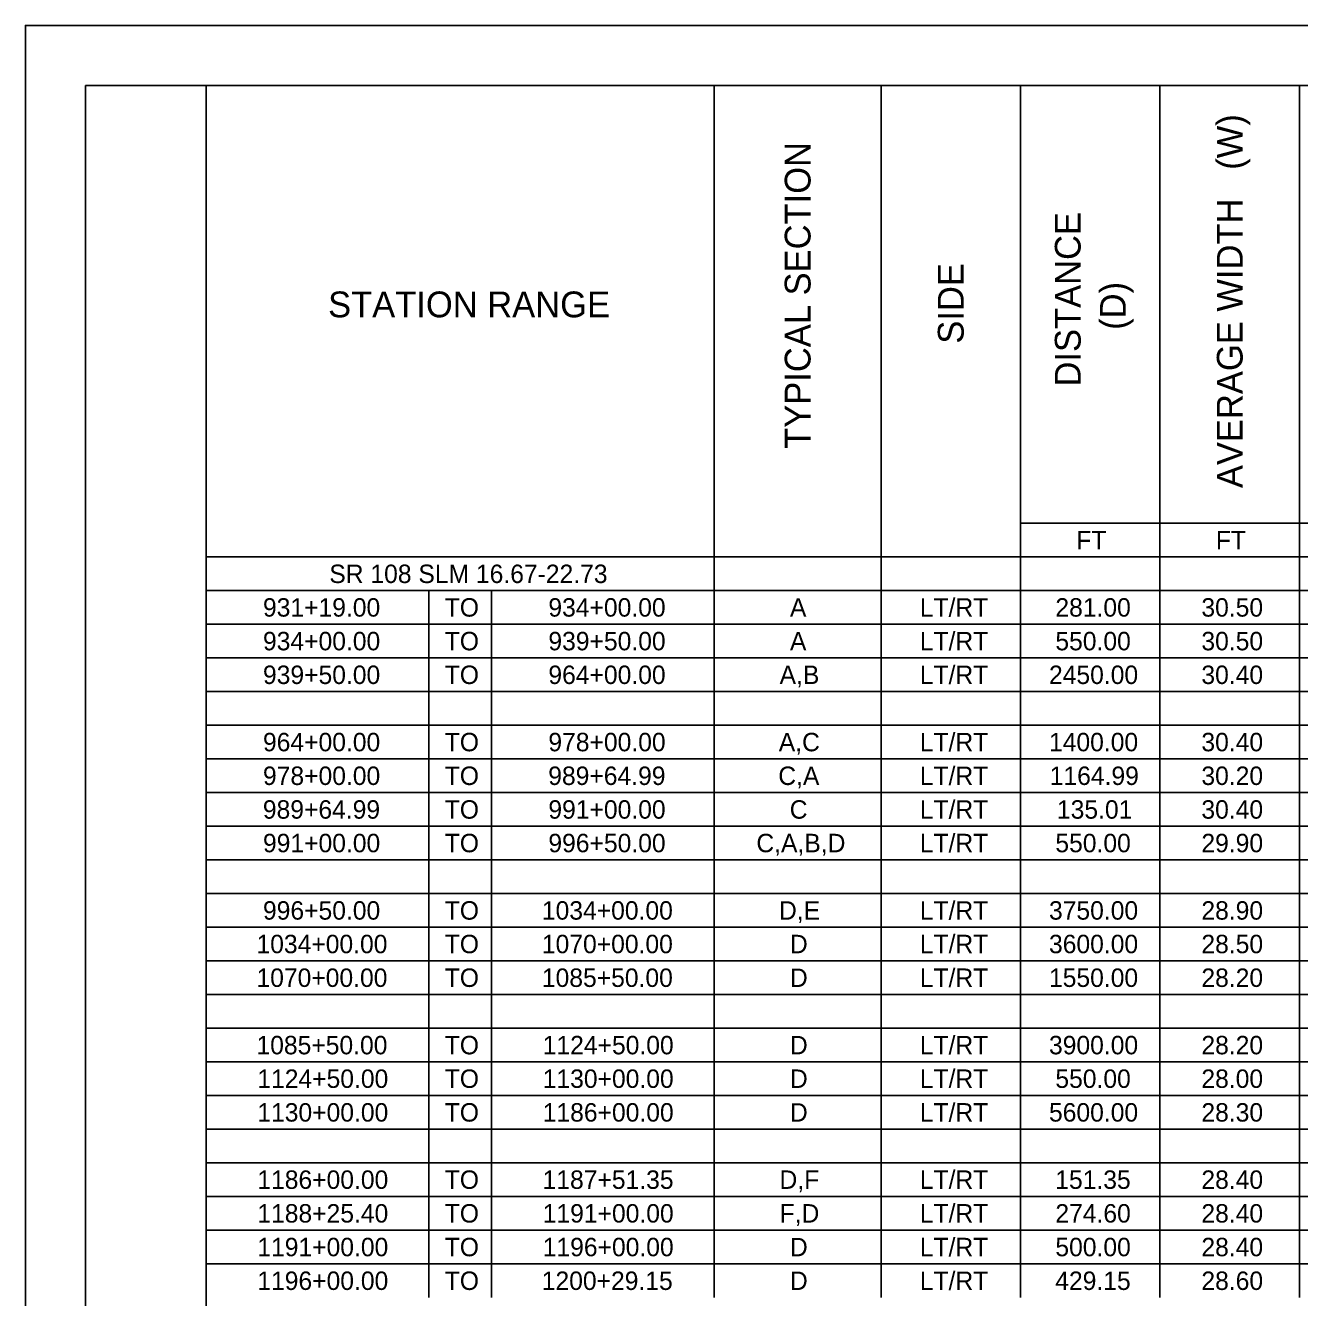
# Model space of a CAD drawing. Extents: x 0 to 34.4, y 0 to 47.
# Drawn here: x 0 to 10.58, y 11.43 to 22 of the extents above; entities that cross this region are included whole.
import ezdxf

# ---------------------------------------------------------------- set-up
doc = ezdxf.new("R2010")
doc.units = 0
for name, color, linetype in [('SH_Border', 7, 'Continuous'), ('SH_Cut_Line', 7, 'Continuous'), ('SH_Text', 7, 'Continuous')]:
    doc.layers.add(name, color=color, linetype=linetype)

msp = doc.modelspace()

# ---------------------------------------------------------------- linework, layer by layer
at = {"layer": 'SH_Border'}
for points in [[(0.5, 21.5), (1.5, 21.5), (1.5, 0.5), (0.5, 0.5)], [(1.5, 21.5), (33.5, 21.5), (33.5, 0.5), (1.5, 0.5)]]:
    msp.add_lwpolyline(points, close=True, dxfattribs=at)
at = {"layer": 'SH_Cut_Line'}
msp.add_lwpolyline([(0, 0), (34, 0), (34, 22), (0, 22)], close=True, dxfattribs=at)
at = {"layer": 'SH_Text'}
for p, q in [((1.5, 21.5), (3.871, 21.5)), ((1.5, 21.5), (1.5, 21.22)), ((3.871, 21.5), (8.267, 21.5)), ((5.722, 21.5), (5.722, 21.22)), ((7.108, 21.5), (7.108, 21.22)), ((8.267, 21.5), (10.584, 21.5)), ((8.267, 21.5), (8.267, 21.22)), ((9.425, 21.5), (9.425, 21.22)), ((10.584, 21.5), (11.743, 21.5)), ((10.584, 21.5), (10.584, 21.22)), ((1.5, 21.22), (1.5, 20.941)), ((5.722, 21.22), (5.722, 20.941)), ((7.108, 21.22), (7.108, 20.941)), ((8.267, 21.22), (8.267, 20.941)), ((9.425, 21.22), (9.425, 20.941)), ((10.584, 21.22), (10.584, 20.941)), ((1.5, 20.941), (1.5, 20.661)), ((5.722, 20.941), (5.722, 20.661)), ((7.108, 20.941), (7.108, 20.661)), ((8.267, 20.941), (8.267, 20.661)), ((9.425, 20.941), (9.425, 20.661)), ((10.584, 20.941), (10.584, 20.661)), ((1.5, 20.661), (1.5, 20.101)), ((5.722, 20.661), (5.722, 20.101)), ((7.108, 20.661), (7.108, 20.101)), ((8.267, 20.661), (8.267, 20.101)), ((9.425, 20.661), (9.425, 20.101)), ((10.584, 20.661), (10.584, 20.101)), ((1.5, 20.101), (1.5, 19.822)), ((5.722, 20.101), (5.722, 19.822)), ((7.108, 20.101), (7.108, 19.822)), ((8.267, 20.101), (8.267, 19.822)), ((9.425, 20.101), (9.425, 19.822)), ((10.584, 20.101), (10.584, 19.822)), ((1.5, 19.822), (1.5, 19.542)), ((5.722, 19.822), (5.722, 19.542)), ((7.108, 19.822), (7.108, 19.542)), ((8.267, 19.822), (8.267, 19.542)), ((9.425, 19.822), (9.425, 19.542)), ((10.584, 19.822), (10.584, 19.542)), ((1.5, 19.542), (1.5, 19.262)), ((5.722, 19.542), (5.722, 19.262)), ((7.108, 19.542), (7.108, 19.262)), ((8.267, 19.542), (8.267, 19.262)), ((9.425, 19.542), (9.425, 19.262)), ((10.584, 19.542), (10.584, 19.262)), ((1.5, 19.262), (1.5, 18.983)), ((5.722, 19.262), (5.722, 18.983)), ((7.108, 19.262), (7.108, 18.983)), ((8.267, 19.262), (8.267, 18.983)), ((9.425, 19.262), (9.425, 18.983)), ((10.584, 19.262), (10.584, 18.983)), ((1.5, 18.983), (1.5, 18.703)), ((5.722, 18.983), (5.722, 18.703)), ((7.108, 18.983), (7.108, 18.703)), ((8.267, 18.983), (8.267, 18.703)), ((9.425, 18.983), (9.425, 18.703)), ((10.584, 18.983), (10.584, 18.703)), ((1.5, 18.703), (1.5, 18.423)), ((5.722, 18.703), (5.722, 18.423)), ((7.108, 18.703), (7.108, 18.423)), ((8.267, 18.703), (8.267, 18.423)), ((9.425, 18.703), (9.425, 18.423)), ((10.584, 18.703), (10.584, 18.423)), ((1.5, 18.423), (1.5, 18.143)), ((5.722, 18.423), (5.722, 18.143)), ((7.108, 18.423), (7.108, 18.143)), ((8.267, 18.423), (8.267, 18.143)), ((9.425, 18.423), (9.425, 18.143)), ((10.584, 18.423), (10.584, 18.143)), ((1.5, 18.143), (1.5, 17.864)), ((5.722, 18.143), (5.722, 17.864)), ((7.108, 18.143), (7.108, 17.864)), ((8.267, 18.143), (8.267, 17.864)), ((9.425, 18.143), (9.425, 17.864)), ((10.584, 18.143), (10.584, 17.864)), ((1.5, 17.864), (1.5, 17.584)), ((5.722, 17.864), (5.722, 17.584)), ((7.108, 17.864), (7.108, 17.584)), ((8.267, 17.864), (10.584, 17.864)), ((8.267, 17.864), (8.267, 17.584)), ((9.425, 17.864), (9.425, 17.584)), ((10.584, 17.864), (11.743, 17.864)), ((10.584, 17.864), (10.584, 17.584)), ((1.5, 17.584), (3.871, 17.584)), ((1.5, 17.584), (1.5, 17.304)), ((3.871, 17.584), (8.267, 17.584)), ((5.722, 17.584), (5.722, 17.304)), ((7.108, 17.584), (7.108, 17.304)), ((8.267, 17.584), (10.584, 17.584)), ((8.267, 17.584), (8.267, 17.304)), ((9.425, 17.584), (9.425, 17.304)), ((10.584, 17.584), (11.743, 17.584)), ((10.584, 17.584), (10.584, 17.304)), ((1.5, 17.304), (3.871, 17.304)), ((1.5, 17.304), (1.5, 17.024)), ((3.351, 17.304), (3.351, 17.024)), ((3.871, 17.304), (8.267, 17.304)), ((3.871, 17.304), (3.871, 17.024)), ((5.722, 17.304), (5.722, 17.024)), ((7.108, 17.304), (7.108, 17.024)), ((8.267, 17.304), (10.584, 17.304)), ((8.267, 17.304), (8.267, 17.024)), ((9.425, 17.304), (9.425, 17.024)), ((10.584, 17.304), (11.743, 17.304)), ((10.584, 17.304), (10.584, 17.024)), ((1.5, 17.024), (3.871, 17.024)), ((1.5, 17.024), (1.5, 16.745)), ((3.351, 17.024), (3.351, 16.745)), ((3.871, 17.024), (8.267, 17.024)), ((3.871, 17.024), (3.871, 16.745)), ((5.722, 17.024), (5.722, 16.745)), ((7.108, 17.024), (7.108, 16.745)), ((8.267, 17.024), (10.584, 17.024)), ((8.267, 17.024), (8.267, 16.745)), ((9.425, 17.024), (9.425, 16.745)), ((10.584, 17.024), (11.743, 17.024)), ((10.584, 17.024), (10.584, 16.745)), ((1.5, 16.745), (3.871, 16.745)), ((1.5, 16.745), (1.5, 16.185)), ((3.351, 16.745), (3.351, 16.185)), ((3.871, 16.745), (8.267, 16.745)), ((3.871, 16.745), (3.871, 16.185)), ((5.722, 16.745), (5.722, 16.185)), ((7.108, 16.745), (7.108, 16.185)), ((8.267, 16.745), (10.584, 16.745)), ((8.267, 16.745), (8.267, 16.185)), ((9.425, 16.745), (9.425, 16.185)), ((10.584, 16.745), (11.743, 16.745)), ((10.584, 16.745), (10.584, 16.185)), ((1.5, 16.465), (3.871, 16.465)), ((3.871, 16.465), (8.267, 16.465)), ((8.267, 16.465), (10.584, 16.465)), ((10.584, 16.465), (11.743, 16.465)), ((1.5, 16.185), (3.871, 16.185)), ((1.5, 16.185), (1.5, 15.906)), ((3.351, 16.185), (3.351, 15.906)), ((3.871, 16.185), (8.267, 16.185)), ((3.871, 16.185), (3.871, 15.906)), ((5.722, 16.185), (5.722, 15.906)), ((7.108, 16.185), (7.108, 15.906)), ((8.267, 16.185), (10.584, 16.185)), ((8.267, 16.185), (8.267, 15.906)), ((9.425, 16.185), (9.425, 15.906)), ((10.584, 16.185), (11.743, 16.185)), ((10.584, 16.185), (10.584, 15.906)), ((1.5, 15.906), (3.871, 15.906)), ((1.5, 15.906), (1.5, 15.626)), ((3.351, 15.906), (3.351, 15.626)), ((3.871, 15.906), (8.267, 15.906)), ((3.871, 15.906), (3.871, 15.626)), ((5.722, 15.906), (5.722, 15.626)), ((7.108, 15.906), (7.108, 15.626)), ((8.267, 15.906), (10.584, 15.906)), ((8.267, 15.906), (8.267, 15.626)), ((9.425, 15.906), (9.425, 15.626)), ((10.584, 15.906), (11.743, 15.906)), ((10.584, 15.906), (10.584, 15.626)), ((1.5, 15.626), (3.871, 15.626)), ((1.5, 15.626), (1.5, 15.346)), ((3.351, 15.626), (3.351, 15.346)), ((3.871, 15.626), (8.267, 15.626)), ((3.871, 15.626), (3.871, 15.346)), ((5.722, 15.626), (5.722, 15.346)), ((7.108, 15.626), (7.108, 15.346)), ((8.267, 15.626), (10.584, 15.626)), ((8.267, 15.626), (8.267, 15.346)), ((9.425, 15.626), (9.425, 15.346)), ((10.584, 15.626), (11.743, 15.626)), ((10.584, 15.626), (10.584, 15.346)), ((1.5, 15.346), (3.871, 15.346)), ((1.5, 15.346), (1.5, 14.787)), ((3.351, 15.346), (3.351, 14.787)), ((3.871, 15.346), (8.267, 15.346)), ((3.871, 15.346), (3.871, 14.787)), ((5.722, 15.346), (5.722, 14.787)), ((7.108, 15.346), (7.108, 14.787)), ((8.267, 15.346), (10.584, 15.346)), ((8.267, 15.346), (8.267, 14.787)), ((9.425, 15.346), (9.425, 14.787)), ((10.584, 15.346), (11.743, 15.346)), ((10.584, 15.346), (10.584, 14.787)), ((1.5, 15.066), (3.871, 15.066)), ((3.871, 15.066), (8.267, 15.066)), ((8.267, 15.066), (10.584, 15.066)), ((10.584, 15.066), (11.743, 15.066)), ((1.5, 14.787), (3.871, 14.787)), ((1.5, 14.787), (1.5, 14.507)), ((3.351, 14.787), (3.351, 14.507)), ((3.871, 14.787), (8.267, 14.787)), ((3.871, 14.787), (3.871, 14.507)), ((5.722, 14.787), (5.722, 14.507)), ((7.108, 14.787), (7.108, 14.507)), ((8.267, 14.787), (10.584, 14.787)), ((8.267, 14.787), (8.267, 14.507)), ((9.425, 14.787), (9.425, 14.507)), ((10.584, 14.787), (11.743, 14.787)), ((10.584, 14.787), (10.584, 14.507)), ((1.5, 14.507), (3.871, 14.507)), ((1.5, 14.507), (1.5, 14.227)), ((3.351, 14.507), (3.351, 14.227)), ((3.871, 14.507), (8.267, 14.507)), ((3.871, 14.507), (3.871, 14.227)), ((5.722, 14.507), (5.722, 14.227)), ((7.108, 14.507), (7.108, 14.227)), ((8.267, 14.507), (10.584, 14.507)), ((8.267, 14.507), (8.267, 14.227)), ((9.425, 14.507), (9.425, 14.227)), ((10.584, 14.507), (11.743, 14.507)), ((10.584, 14.507), (10.584, 14.227)), ((1.5, 14.227), (3.871, 14.227)), ((1.5, 14.227), (1.5, 13.948)), ((3.351, 14.227), (3.351, 13.948)), ((3.871, 14.227), (8.267, 14.227)), ((3.871, 14.227), (3.871, 13.948)), ((5.722, 14.227), (5.722, 13.948)), ((7.108, 14.227), (7.108, 13.948)), ((8.267, 14.227), (10.584, 14.227)), ((8.267, 14.227), (8.267, 13.948)), ((9.425, 14.227), (9.425, 13.948)), ((10.584, 14.227), (11.743, 14.227)), ((10.584, 14.227), (10.584, 13.948)), ((1.5, 13.948), (3.871, 13.948)), ((1.5, 13.948), (1.5, 13.108)), ((3.351, 13.948), (3.351, 13.108)), ((3.871, 13.948), (8.267, 13.948)), ((3.871, 13.948), (3.871, 13.108)), ((5.722, 13.948), (5.722, 13.108)), ((7.108, 13.948), (7.108, 13.108)), ((8.267, 13.948), (10.584, 13.948)), ((8.267, 13.948), (8.267, 13.108)), ((9.425, 13.948), (9.425, 13.108)), ((10.584, 13.948), (11.743, 13.948)), ((10.584, 13.948), (10.584, 13.108)), ((1.5, 13.668), (3.871, 13.668)), ((3.871, 13.668), (8.267, 13.668)), ((8.267, 13.668), (10.584, 13.668)), ((10.584, 13.668), (11.743, 13.668)), ((1.5, 13.388), (3.871, 13.388)), ((3.871, 13.388), (8.267, 13.388)), ((8.267, 13.388), (10.584, 13.388)), ((10.584, 13.388), (11.743, 13.388)), ((1.5, 13.108), (3.871, 13.108)), ((1.5, 13.108), (1.5, 12.829)), ((3.351, 13.108), (3.351, 12.829)), ((3.871, 13.108), (8.267, 13.108)), ((3.871, 13.108), (3.871, 12.829)), ((5.722, 13.108), (5.722, 12.829)), ((7.108, 13.108), (7.108, 12.829)), ((8.267, 13.108), (10.584, 13.108)), ((8.267, 13.108), (8.267, 12.829)), ((9.425, 13.108), (9.425, 12.829)), ((10.584, 13.108), (11.743, 13.108)), ((10.584, 13.108), (10.584, 12.829)), ((1.5, 12.829), (3.871, 12.829)), ((1.5, 12.829), (1.5, 11.71)), ((3.351, 12.829), (3.351, 11.71)), ((3.871, 12.829), (8.267, 12.829)), ((3.871, 12.829), (3.871, 11.71)), ((5.722, 12.829), (5.722, 11.71)), ((7.108, 12.829), (7.108, 11.71)), ((8.267, 12.829), (10.584, 12.829)), ((8.267, 12.829), (8.267, 11.71)), ((9.425, 12.829), (9.425, 11.71)), ((10.584, 12.829), (11.743, 12.829)), ((10.584, 12.829), (10.584, 11.71)), ((1.5, 12.549), (3.871, 12.549)), ((3.871, 12.549), (8.267, 12.549)), ((8.267, 12.549), (10.584, 12.549)), ((10.584, 12.549), (11.743, 12.549)), ((1.5, 12.269), (3.871, 12.269)), ((3.871, 12.269), (8.267, 12.269)), ((8.267, 12.269), (10.584, 12.269)), ((10.584, 12.269), (11.743, 12.269)), ((1.5, 11.99), (3.871, 11.99)), ((3.871, 11.99), (8.267, 11.99)), ((8.267, 11.99), (10.584, 11.99)), ((10.584, 11.99), (11.743, 11.99)), ((1.5, 11.71), (3.871, 11.71)), ((1.5, 11.71), (1.5, 11.43)), ((3.351, 11.71), (3.351, 11.43)), ((3.871, 11.71), (8.267, 11.71)), ((3.871, 11.71), (3.871, 11.43)), ((5.722, 11.71), (5.722, 11.43)), ((7.108, 11.71), (7.108, 11.43)), ((8.267, 11.71), (10.584, 11.71)), ((8.267, 11.71), (8.267, 11.43)), ((9.425, 11.71), (9.425, 11.43)), ((10.584, 11.71), (11.743, 11.71)), ((10.584, 11.71), (10.584, 11.43))]:
    msp.add_line(p, q, dxfattribs=at)

# ---------------------------------------------------------------- texts
for s, height, p in [('AVERAGE WIDTH   (W)', 0.21445, (10.112, 18.156)), ('TYPICAL SECTION', 0.21445, (6.522, 18.482)), ('DISTANCE                                                                                                        ', 0.214452, (8.766, 19)), ('SIDE', 0.2145, (7.794, 19.356)), ('(D)', 0.2145, (9.141, 19.471))]:
    msp.add_text(s, height=height, rotation=90, dxfattribs=at).set_placement(p)
for s, height, p in [('STATION RANGE', 0.21445, (2.514, 19.575)), ('FT', 0.1532, (8.73, 17.647)), ('FT', 0.1532, (9.889, 17.647)), ('SR 108 SLM 16.67-22.73', 0.15318, (2.524, 17.367)), ('931+19.00', 0.1532, (1.973, 17.088)), ('TO', 0.1532, (3.483, 17.088)), ('934+00.00', 0.1532, (4.344, 17.088)), ('A', 0.153, (6.351, 17.088)), ('LT/RT', 0.1532, (7.43, 17.088)), ('281.00', 0.1532, (8.556, 17.088)), ('30.50', 0.1532, (9.769, 17.088)), ('934+00.00', 0.1532, (1.973, 16.808)), ('TO', 0.1532, (3.483, 16.808)), ('939+50.00', 0.1532, (4.344, 16.808)), ('A', 0.153, (6.351, 16.808)), ('LT/RT', 0.1532, (7.43, 16.808)), ('550.00', 0.1532, (8.556, 16.808)), ('30.50', 0.1532, (9.769, 16.808)), ('939+50.00', 0.1532, (1.973, 16.528)), ('TO', 0.1532, (3.483, 16.528)), ('964+00.00', 0.1532, (4.344, 16.528)), ('A,B', 0.1532, (6.265, 16.528)), ('LT/RT', 0.1532, (7.43, 16.528)), ('2450.00', 0.1532, (8.503, 16.528)), ('30.40', 0.1532, (9.769, 16.528)), ('964+00.00', 0.1532, (1.973, 15.969)), ('TO', 0.1532, (3.483, 15.969)), ('978+00.00', 0.1532, (4.344, 15.969)), ('A,C', 0.1532, (6.258, 15.969)), ('LT/RT', 0.1532, (7.43, 15.969)), ('1400.00', 0.1532, (8.503, 15.969)), ('30.40', 0.1532, (9.769, 15.969)), ('978+00.00', 0.1532, (1.973, 15.689)), ('TO', 0.1532, (3.483, 15.689)), ('989+64.99', 0.1532, (4.343, 15.689)), ('C,A', 0.1532, (6.254, 15.689)), ('LT/RT', 0.1532, (7.43, 15.689)), ('1164.99', 0.1532, (8.509, 15.689)), ('30.20', 0.1532, (9.769, 15.689)), ('989+64.99', 0.1532, (1.972, 15.409)), ('TO', 0.1532, (3.483, 15.409)), ('991+00.00', 0.1532, (4.344, 15.409)), ('C', 0.153, (6.349, 15.409)), ('LT/RT', 0.1532, (7.43, 15.409)), ('135.01', 0.1532, (8.569, 15.409)), ('30.40', 0.1532, (9.769, 15.409)), ('991+00.00', 0.1532, (1.973, 15.13)), ('TO', 0.1532, (3.483, 15.13)), ('996+50.00', 0.1532, (4.344, 15.13)), ('C,A,B,D', 0.1532, (6.072, 15.13)), ('LT/RT', 0.1532, (7.43, 15.13)), ('550.00', 0.1532, (8.556, 15.13)), ('29.90', 0.1532, (9.769, 15.13)), ('996+50.00', 0.1532, (1.973, 14.57)), ('TO', 0.1532, (3.483, 14.57)), ('1034+00.00', 0.1532, (4.29, 14.57)), ('D,E', 0.1532, (6.26, 14.57)), ('LT/RT', 0.1532, (7.43, 14.57)), ('3750.00', 0.1532, (8.503, 14.57)), ('28.90', 0.1532, (9.769, 14.57)), ('1034+00.00', 0.1532, (1.919, 14.291)), ('TO', 0.1532, (3.483, 14.291)), ('1070+00.00', 0.1532, (4.29, 14.291)), ('D', 0.153, (6.351, 14.291)), ('LT/RT', 0.1532, (7.43, 14.291)), ('3600.00', 0.1532, (8.503, 14.291)), ('28.50', 0.1532, (9.769, 14.291)), ('1070+00.00', 0.1532, (1.919, 14.011)), ('TO', 0.1532, (3.483, 14.011)), ('1085+50.00', 0.1532, (4.29, 14.011)), ('D', 0.153, (6.351, 14.011)), ('LT/RT', 0.1532, (7.43, 14.011)), ('1550.00', 0.1532, (8.503, 14.011)), ('28.20', 0.1532, (9.769, 14.011)), ('1085+50.00', 0.1532, (1.919, 13.451)), ('TO', 0.1532, (3.483, 13.451)), ('1124+50.00', 0.1532, (4.297, 13.451)), ('D', 0.153, (6.351, 13.451)), ('LT/RT', 0.1532, (7.43, 13.451)), ('3900.00', 0.1532, (8.503, 13.451)), ('28.20', 0.1532, (9.769, 13.451)), ('1124+50.00', 0.1532, (1.926, 13.172)), ('TO', 0.1532, (3.483, 13.172)), ('1130+00.00', 0.1532, (4.297, 13.172)), ('D', 0.153, (6.351, 13.172)), ('LT/RT', 0.1532, (7.43, 13.172)), ('550.00', 0.1532, (8.556, 13.172)), ('28.00', 0.1532, (9.769, 13.172)), ('1130+00.00', 0.1532, (1.926, 12.892)), ('TO', 0.1532, (3.483, 12.892)), ('1186+00.00', 0.1532, (4.297, 12.892)), ('D', 0.153, (6.351, 12.892)), ('LT/RT', 0.1532, (7.43, 12.892)), ('5600.00', 0.1532, (8.503, 12.892)), ('28.30', 0.1532, (9.769, 12.892)), ('LT/RT', 0.1532, (7.43, 12.333)), ('1186+00.00', 0.1532, (1.926, 12.333)), ('TO', 0.1532, (3.483, 12.333)), ('1187+51.35', 0.1532, (4.296, 12.333)), ('D,F', 0.1532, (6.264, 12.333)), ('151.35', 0.1532, (8.555, 12.333)), ('28.40', 0.1532, (9.769, 12.333)), ('1188+25.40', 0.1532, (1.926, 12.053)), ('TO', 0.1532, (3.483, 12.053)), ('1191+00.00', 0.1532, (4.297, 12.053)), ('F,D', 0.1532, (6.265, 12.053)), ('LT/RT', 0.1532, (7.43, 12.053)), ('274.60', 0.1532, (8.556, 12.053)), ('28.40', 0.1532, (9.769, 12.053)), ('1191+00.00', 0.1532, (1.926, 11.773)), ('TO', 0.1532, (3.483, 11.773)), ('1196+00.00', 0.1532, (4.297, 11.773)), ('D', 0.153, (6.351, 11.773)), ('LT/RT', 0.1532, (7.43, 11.773)), ('500.00', 0.1532, (8.556, 11.773)), ('28.40', 0.1532, (9.769, 11.773)), ('1196+00.00', 0.1532, (1.926, 11.493)), ('TO', 0.1532, (3.483, 11.493)), ('1200+29.15', 0.1532, (4.289, 11.493)), ('D', 0.153, (6.351, 11.493)), ('LT/RT', 0.1532, (7.43, 11.493)), ('429.15', 0.1532, (8.555, 11.493)), ('28.60', 0.1532, (9.769, 11.493))]:
    msp.add_text(s, height=height, dxfattribs=at).set_placement(p)

doc.saveas('drawing.dxf')
